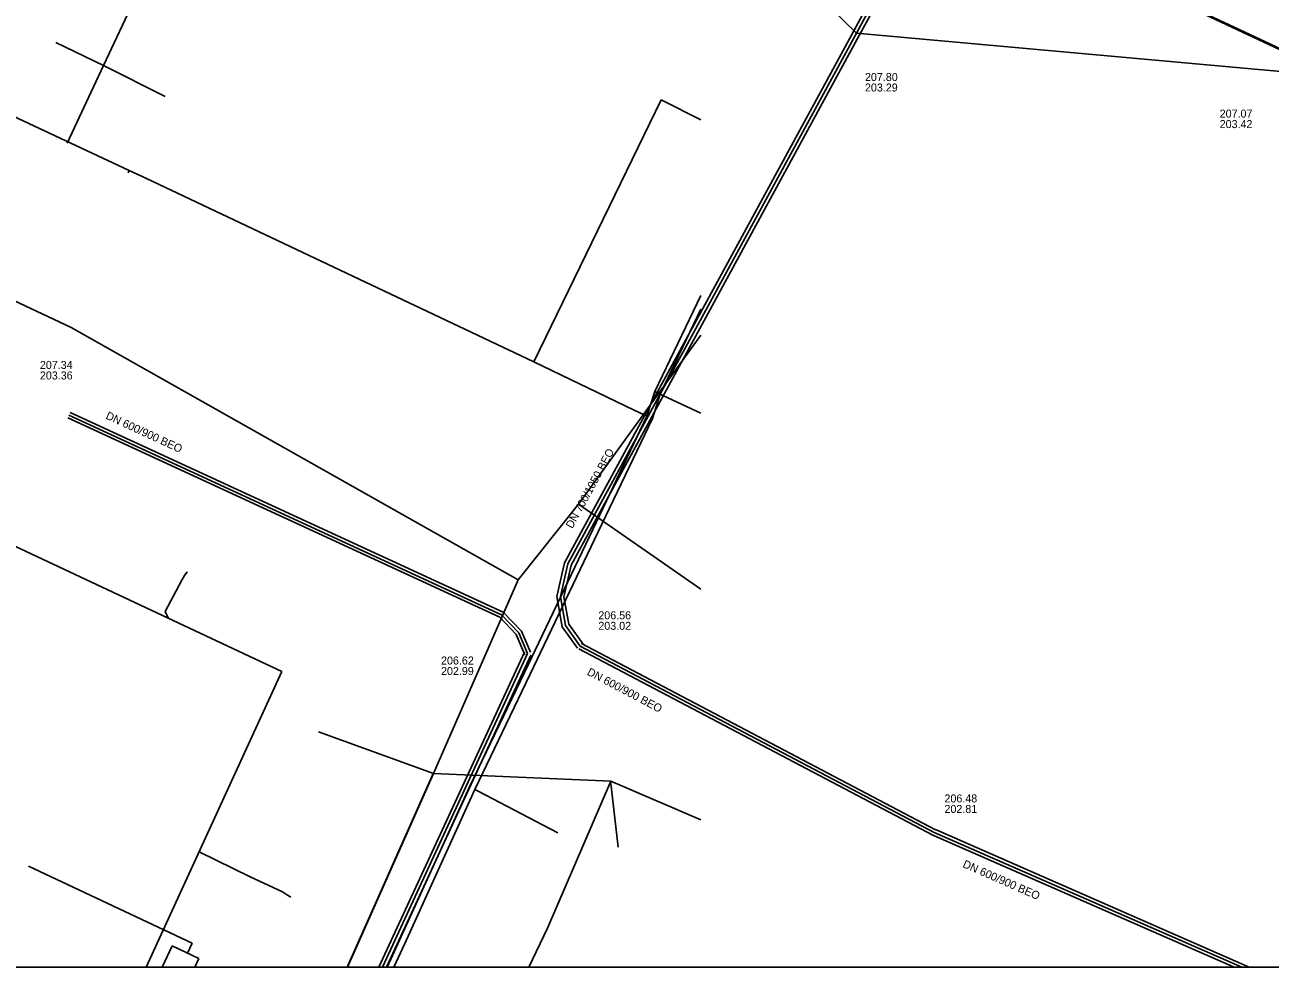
# Model space of a CAD drawing. Extents: x -600309 to -598967, y -1161267 to -1160292.
# Drawn here: x -600189.6 to -600065.1, y -1161267 to -1161172.8 of the extents above; entities that cross this region are included whole.
import ezdxf

# ---------------------------------------------------------------- set-up
doc = ezdxf.new("R2010")
doc.units = 0
for name, color, linetype in [('Vrstva 1', 7, 'Continuous'), ('Vrstva 10', 7, 'Continuous'), ('Vrstva 12', 7, 'Continuous'), ('Vrstva 13', 7, 'Continuous'), ('Vrstva 50', 7, 'Continuous'), ('Vrstva 58', 7, 'Continuous'), ('Vrstva 63', 7, 'Continuous'), ('Vrstva 9', 7, 'Continuous')]:
    doc.layers.add(name, color=color, linetype=linetype)

msp = doc.modelspace()

# ---------------------------------------------------------------- linework, layer by layer
at = {"layer": 'Vrstva 1'}
for p, q in [((-600181.75, -1161176.89), (-600176.88, -1161166.53)), ((-600186.53, -1161174.58), (-600181.75, -1161176.89)), ((-600185.38, -1161184.67), (-600181.75, -1161176.89)), ((-600181.75, -1161176.89), (-600175.58, -1161179.98)), ((-600228.59, -1161182.64), (-600184.98, -1161203.07)), ((-600122.04, -1161201.26), (-600126.1, -1161209.74)), ((-600184.98, -1161203.07), (-600140.29, -1161228.32)), ((-600134.27, -1161220.75), (-600122.04, -1161203.86)), ((-600126.87, -1161212.2), (-600126.1, -1161209.74)), ((-600126.87, -1161212.2), (-600131.93, -1161222.76)), ((-600134.27, -1161220.75), (-600140.29, -1161228.32)), ((-600134.27, -1161220.75), (-600122.04, -1161229.25)), ((-600131.93, -1161222.76), (-600139.13, -1161237.82)), ((-600140.29, -1161228.32), (-600148.78, -1161247.68)), ((-600139.13, -1161237.82), (-600144.62, -1161249.29)), ((-600148.78, -1161247.68), (-600160.26, -1161243.51)), ((-600148.77, -1161247.62), (-600157.41, -1161267.03)), ((-600148.78, -1161247.68), (-600157.38, -1161267.03)), ((-600131.03, -1161248.44), (-600148.78, -1161247.68)), ((-600131.03, -1161248.44), (-600137.37, -1161263.14)), ((-600131.07, -1161248.38), (-600130.31, -1161255.03)), ((-600122.04, -1161252.3), (-600131.03, -1161248.44)), ((-600144.62, -1161249.29), (-600151.64, -1161264.67)), ((-600144.31, -1161249.45), (-600144.62, -1161249.29)), ((-600136.33, -1161253.6), (-600144.31, -1161249.45)), ((-600189.25, -1161256.93), (-600172.89, -1161264.63)), ((-600137.37, -1161263.14), (-600139.22, -1161267.03)), ((-600175.89, -1161267.03), (-600174.9, -1161264.91)), ((-600174.9, -1161264.91), (-600172.23, -1161266.18)), ((-600173.37, -1161265.64), (-600172.89, -1161264.63)), ((-600151.64, -1161264.67), (-600152.72, -1161267.03)), ((-600172.23, -1161266.18), (-600172.63, -1161267.03))]:
    msp.add_line(p, q, dxfattribs=at)
for points in [[(-600204.8, -1161218.32), (-600163.93, -1161237.49), (-600177.48, -1161267.03)], [(-600173.4, -1161227.5), (-600173.66, -1161227.88), (-600173.92, -1161228.34), (-600175.6, -1161231.47), (-600175.27, -1161232.17)], [(-600172.2, -1161255.51), (-600167.11, -1161258.01), (-600163.85, -1161259.52), (-600163.37, -1161259.84), (-600163.03, -1161260.03)]]:
    msp.add_lwpolyline(points, dxfattribs=at)
at = {"layer": 'Vrstva 10'}
for p, q in [((-600106.78, -1161173.48), (-600090.03, -1161142.75)), ((-600089.41, -1161143.09), (-600106.16, -1161173.82)), ((-600098.84, -1161253.83), (-600134.23, -1161235.21)), ((-600133.95, -1161234.67), (-600098.56, -1161253.3)), ((-600154.23, -1161267.03), (-600139.68, -1161235.53)), ((-600139.04, -1161235.83), (-600153.46, -1161267.03)), ((-600068.7, -1161267.03), (-600098.82, -1161253.84)), ((-600098.58, -1161253.29), (-600067.2, -1161267.03))]:
    msp.add_line(p, q, dxfattribs=at)
for points in [[(-600134.38, -1161235.14), (-600135.9, -1161233.02), (-600136.43, -1161229.98), (-600135.65, -1161226.6), (-600106.78, -1161173.48)], [(-600106.16, -1161173.82), (-600134.99, -1161226.85), (-600134.99, -1161226.85), (-600135.72, -1161230), (-600135.24, -1161232.74), (-600133.81, -1161234.74)], [(-600185.09, -1161211.57), (-600141.79, -1161231.56), (-600141.79, -1161231.56), (-600139.98, -1161233.45), (-600139.08, -1161235.56)], [(-600139.64, -1161235.8), (-600140.49, -1161233.78), (-600142.14, -1161232.06), (-600185.34, -1161212.11)]]:
    msp.add_lwpolyline(points, dxfattribs=at)
at = {"layer": 'Vrstva 12'}
msp.add_lwpolyline([(-600091.26, -1161162.39), (-600075.91, -1161169.65), (-600048.6, -1161182.47), (-600008.54, -1161201.33), (-600000, -1161205.41)], dxfattribs=at)
at = {"layer": 'Vrstva 13'}
for p, q in [((-600208.98, -1161173.43), (-600179.2, -1161187.38)), ((-600126.01, -1161180.31), (-600138.72, -1161206.51)), ((-600122.04, -1161182.32), (-600126.01, -1161180.31)), ((-600179.2, -1161187.38), (-600179.31, -1161187.63)), ((-600179.2, -1161187.38), (-600177.46, -1161188.2)), ((-600177.46, -1161188.2), (-600138.72, -1161206.51)), ((-600122.04, -1161199.89), (-600126.63, -1161209.48)), ((-600138.72, -1161206.51), (-600128.69, -1161211.34)), ((-600127.42, -1161211.95), (-600126.63, -1161209.48)), ((-600125.83, -1161209.87), (-600126.63, -1161209.48)), ((-600122.04, -1161211.66), (-600125.83, -1161209.87)), ((-600128.69, -1161211.34), (-600127.7, -1161211.82)), ((-600127.42, -1161211.95), (-600132.47, -1161222.53)), ((-600127.7, -1161211.82), (-600127.42, -1161211.95)), ((-600132.47, -1161222.53), (-600139.68, -1161237.59)), ((-600139.68, -1161237.59), (-600145.15, -1161249.01)), ((-600153.39, -1161267.03), (-600145.15, -1161249.01))]:
    msp.add_line(p, q, dxfattribs=at)
at = {"layer": 'Vrstva 50'}
msp.add_lwpolyline([(-600087.86, -1161156.14), (-600090.75, -1161162.78), (-599998.17, -1161206.22), (-599999.77, -1161209.62), (-599915.67, -1161249.08)], dxfattribs=at)
at = {"layer": 'Vrstva 58'}
msp.add_lwpolyline([(-600027.63, -1160996.29), (-600029.2, -1160995.83), (-600029.66, -1160996.07), (-600030.11, -1160996.32), (-600036.84, -1161021.84), (-600043.12, -1161045.88), (-600052.22, -1161080.05), (-600057.33, -1161099.71), (-600059.1, -1161105.42), (-600059.99, -1161108.3), (-600061.48, -1161110.47), (-600071.8, -1161125.57), (-600082.77, -1161141.62), (-600082.77, -1161141.62), (-600084.31, -1161147.58), (-600084.38, -1161147.84), (-600085, -1161150.28), (-600087.29, -1161155.08), (-600087.87, -1161156.15), (-600087.87, -1161156.15), (-600090.76, -1161162.78), (-599998.18, -1161206.22), (-599999.78, -1161209.62), (-599877.43, -1161267.03)], dxfattribs=at)
at = {"layer": 'Vrstva 63'}
msp.add_lwpolyline([(-600308.54, -1160292.35), (-598967.11, -1160292.35), (-598967.11, -1161267.03), (-600308.54, -1161267.03)], close=True, dxfattribs=at)
at = {"layer": 'Vrstva 9'}
for p, q in [((-600089.72, -1161142.92), (-600106.47, -1161173.65)), ((-600134.55, -1161146.36), (-600106.47, -1161173.65)), ((-600063.29, -1161177.55), (-600106.47, -1161173.65)), ((-600134.09, -1161234.94), (-600098.7, -1161253.57)), ((-600139.36, -1161235.68), (-600153.85, -1161267.03)), ((-600098.7, -1161253.57), (-600067.95, -1161267.03))]:
    msp.add_line(p, q, dxfattribs=at)
for points in [[(-600106.47, -1161173.65), (-600135.32, -1161226.73), (-600136.08, -1161229.99), (-600135.57, -1161232.88), (-600134.09, -1161234.94)], [(-600185.22, -1161211.84), (-600141.96, -1161231.81), (-600140.24, -1161233.61), (-600139.36, -1161235.68)]]:
    msp.add_lwpolyline(points, dxfattribs=at)

# ---------------------------------------------------------------- texts
at = {"layer": 'Vrstva 12'}
for s, p in [('207.80', (-600105.62, -1161178.44)), ('203.29', (-600105.62, -1161179.49)), ('207.07', (-600070.15, -1161182.1)), ('203.42', (-600070.15, -1161183.15)), ('207.34', (-600188.12, -1161207.23)), ('203.36', (-600188.12, -1161208.28)), ('206.56', (-600132.28, -1161232.26)), ('203.02', (-600132.28, -1161233.31)), ('206.62', (-600148.01, -1161236.78)), ('202.99', (-600148.01, -1161237.83)), ('206.48', (-600097.67, -1161250.57)), ('202.81', (-600097.67, -1161251.62))]:
    msp.add_text(s, height=0.8, dxfattribs=at).set_placement(p)
for s, rotation, p in [('DN 600/900 BEO', 335.2148, (-600181.61, -1161212.18)), ('DN 700/1050 BEO', 61.4778, (-600134.89, -1161223.25)), ('DN 600/900 BEO', 332.2429, (-600133.48, -1161237.77)), ('DN 600/900 BEO', 336.3512, (-600095.92, -1161257.02))]:
    msp.add_text(s, height=0.8, rotation=rotation, dxfattribs=at).set_placement(p)

doc.saveas('drawing.dxf')
